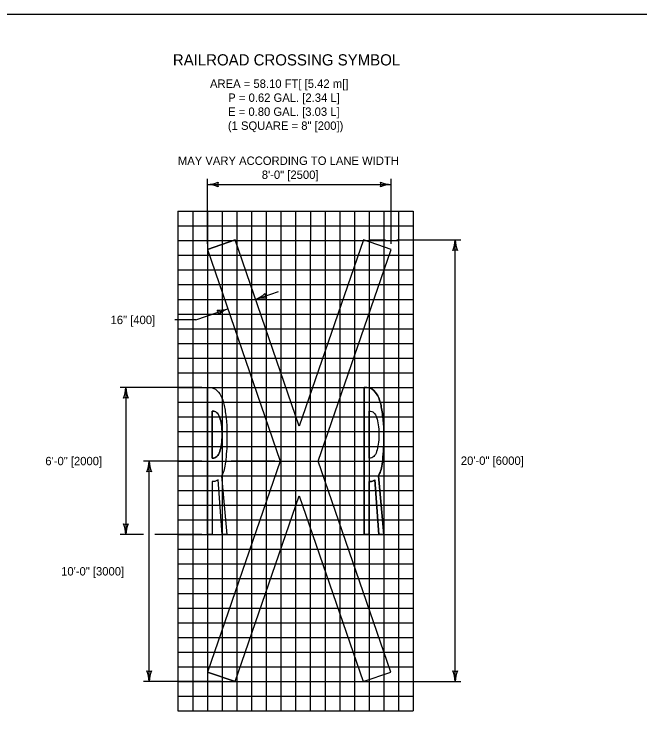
# Model space of a CAD drawing. Extents: x 49948.7 to 50021, y 49977 to 50017.6.
# Drawn here: x 50007.81 to 50012.28, y 49993.97 to 49999 of the extents above; entities that cross this region are included whole.
import ezdxf

# ---------------------------------------------------------------- set-up
doc = ezdxf.new("R2010")
doc.units = 0
for name, color, linetype in [('Level 1', 7, 'Continuous'), ('Level 2', 7, 'Continuous'), ('Level 3', 7, 'Continuous'), ('Level 9', 7, 'Continuous')]:
    doc.layers.add(name, color=color, linetype=linetype)

msp = doc.modelspace()

# ---------------------------------------------------------------- linework, layer by layer
at = {"layer": 'Level 1'}
for p, q in [((50009.1932, 49997.3186), (50009.3909, 49997.3867)), ((50009.3909, 49997.3867), (50009.1932, 49997.3186)), ((50009.8495, 49996.0553), (50009.3909, 49997.3867)), ((50009.8495, 49996.0553), (50009.3909, 49997.3867)), ((50010.3081, 49997.3869), (50009.8495, 49996.0553)), ((50010.3081, 49997.3869), (50009.8495, 49996.0553)), ((50010.5058, 49997.3188), (50010.3081, 49997.3869)), ((50010.5058, 49997.3188), (50010.3081, 49997.3869)), ((50009.1932, 49997.3186), (50009.7138, 49995.8068)), ((50009.1932, 49997.3186), (50009.7138, 49995.8069)), ((50009.1932, 49997.3186), (50009.7138, 49995.8069)), ((50009.9851, 49995.8069), (50010.5058, 49997.3188)), ((50009.9851, 49995.8069), (50010.5058, 49997.3188)), ((50009.1932, 49995.2818), (50009.1932, 49996.3318)), ((50009.1932, 49995.2818), (50009.1932, 49996.3318)), ((50010.3133, 49995.2818), (50010.3133, 49996.3319)), ((50010.3133, 49996.3319), (50010.3133, 49995.2818)), ((50009.2281, 49995.8278), (50009.2281, 49996.1638)), ((50009.2281, 49996.1638), (50009.2281, 49995.8278)), ((50010.3482, 49995.8278), (50010.3482, 49996.1638)), ((50010.3482, 49995.8278), (50010.3482, 49996.1638)), ((50009.7138, 49995.8068), (50009.1949, 49994.2999)), ((50009.7138, 49995.8068), (50009.1949, 49994.2999)), ((50010.504, 49994.2999), (50009.9851, 49995.8068)), ((50010.504, 49994.2999), (50009.9851, 49995.8068)), ((50009.298, 49995.2818), (50009.2692, 49995.673)), ((50009.298, 49995.2818), (50009.2692, 49995.673)), ((50009.2947, 49995.7018), (50009.3329, 49995.2818)), ((50009.2947, 49995.7018), (50009.3329, 49995.2818)), ((50010.4181, 49995.2818), (50010.3893, 49995.673)), ((50010.3893, 49995.673), (50010.4181, 49995.2818)), ((50010.4148, 49995.7018), (50010.453, 49995.2818)), ((50010.453, 49995.2818), (50010.4148, 49995.7018)), ((50009.2281, 49995.6598), (50009.2281, 49995.2818)), ((50009.2281, 49995.6598), (50009.2281, 49995.2818)), ((50010.3482, 49995.6598), (50010.3482, 49995.2818)), ((50010.3482, 49995.2818), (50010.3482, 49995.6598)), ((50009.3926, 49994.2319), (50009.8495, 49995.5584)), ((50009.3926, 49994.2319), (50009.8495, 49995.5584)), ((50009.8495, 49995.5584), (50010.3063, 49994.2319)), ((50009.8495, 49995.5584), (50010.3063, 49994.2319)), ((50009.2281, 49995.2818), (50009.1932, 49995.2818)), ((50009.2281, 49995.2818), (50009.1932, 49995.2818)), ((50009.3329, 49995.2818), (50009.298, 49995.2818)), ((50009.3329, 49995.2818), (50009.298, 49995.2818)), ((50010.3482, 49995.2818), (50010.3133, 49995.2818)), ((50010.3133, 49995.2818), (50010.3482, 49995.2818)), ((50010.453, 49995.2818), (50010.4181, 49995.2818)), ((50010.4181, 49995.2818), (50010.453, 49995.2818)), ((50009.3926, 49994.2319), (50009.1949, 49994.2999)), ((50009.1949, 49994.2999), (50009.3926, 49994.2319)), ((50010.3063, 49994.2319), (50010.504, 49994.2999)), ((50010.3063, 49994.2319), (50010.504, 49994.2999))]:
    msp.add_line(p, q, dxfattribs=at)
msp.add_lwpolyline([(49999.3835, 49998.9992), (50016.7501, 49998.9992), (50016.7501, 49987.7988), (49999.3835, 49987.7988)], close=True, dxfattribs=at)
for points in [[(50009.1932, 49996.3318), (50009.2207, 49996.3343), (50009.2513, 49996.3249), (50009.2939, 49996.2761), (50009.3133, 49996.2081), (50009.3292, 49996.109), (50009.3333, 49996.0383), (50009.3329, 49995.9958)], [(50009.1932, 49996.3318), (50009.2207, 49996.3343), (50009.2513, 49996.3249), (50009.2939, 49996.2761), (50009.3133, 49996.2081), (50009.3292, 49996.109), (50009.3333, 49996.0383), (50009.3329, 49995.9958)], [(50010.3133, 49996.3319), (50010.3407, 49996.3343), (50010.3713, 49996.3249), (50010.414, 49996.2761), (50010.4333, 49996.2081), (50010.4493, 49996.109), (50010.4534, 49996.0383), (50010.453, 49995.9958)], [(50010.453, 49995.9958), (50010.4534, 49996.0383), (50010.4493, 49996.109), (50010.4333, 49996.2081), (50010.414, 49996.2761), (50010.3713, 49996.3249), (50010.3407, 49996.3343), (50010.3133, 49996.3319)], [(50009.2281, 49996.1638), (50009.2422, 49996.1638), (50009.263, 49996.1567), (50009.2834, 49996.1201), (50009.2941, 49996.0668), (50009.2985, 49996.0246), (50009.298, 49995.9958)], [(50009.298, 49995.9958), (50009.2985, 49996.0246), (50009.2941, 49996.0668), (50009.2834, 49996.1201), (50009.263, 49996.1567), (50009.2422, 49996.1638), (50009.2281, 49996.1638)], [(50010.3482, 49996.1638), (50010.3622, 49996.1638), (50010.383, 49996.1567), (50010.4034, 49996.1201), (50010.4142, 49996.0668), (50010.4186, 49996.0246), (50010.4181, 49995.9958)], [(50010.3482, 49996.1638), (50010.3622, 49996.1638), (50010.383, 49996.1567), (50010.4034, 49996.1201), (50010.4142, 49996.0668), (50010.4186, 49996.0246), (50010.4181, 49995.9958)], [(50009.298, 49995.9958), (50009.2985, 49995.9671), (50009.2941, 49995.9248), (50009.2834, 49995.8715), (50009.263, 49995.835), (50009.2422, 49995.8279), (50009.2281, 49995.8278)], [(50009.2281, 49995.8278), (50009.2422, 49995.8279), (50009.263, 49995.835), (50009.2834, 49995.8715), (50009.2941, 49995.9248), (50009.2985, 49995.9671), (50009.298, 49995.9958)], [(50009.3329, 49995.9958), (50009.3335, 49995.9537), (50009.3319, 49995.8976), (50009.3249, 49995.8134), (50009.3176, 49995.7551), (50009.3023, 49995.7145), (50009.2947, 49995.7018), (50009.2947, 49995.7018)], [(50009.3329, 49995.9958), (50009.3335, 49995.9537), (50009.3319, 49995.8976), (50009.3249, 49995.8134), (50009.3176, 49995.7551), (50009.3023, 49995.7145), (50009.2947, 49995.7018), (50009.2947, 49995.7018)], [(50010.4181, 49995.9958), (50010.4186, 49995.9671), (50010.4142, 49995.9248), (50010.4034, 49995.8716), (50010.383, 49995.835), (50010.3622, 49995.8279), (50010.3482, 49995.8278)], [(50010.4181, 49995.9958), (50010.4186, 49995.9671), (50010.4142, 49995.9248), (50010.4034, 49995.8716), (50010.383, 49995.835), (50010.3622, 49995.8279), (50010.3482, 49995.8278)], [(50010.453, 49995.9958), (50010.4536, 49995.9537), (50010.452, 49995.8976), (50010.445, 49995.8134), (50010.4377, 49995.7551), (50010.4224, 49995.7145), (50010.4148, 49995.7018), (50010.4148, 49995.7018)], [(50010.4148, 49995.7018), (50010.4148, 49995.7018), (50010.4224, 49995.7145), (50010.4377, 49995.7551), (50010.445, 49995.8134), (50010.452, 49995.8976), (50010.4536, 49995.9537), (50010.453, 49995.9958)], [(50009.2692, 49995.673), (50009.2692, 49995.673), (50009.2571, 49995.6642), (50009.2436, 49995.6601), (50009.2281, 49995.6598)], [(50009.2692, 49995.673), (50009.2692, 49995.673), (50009.2571, 49995.6642), (50009.2436, 49995.6601), (50009.2281, 49995.6598)], [(50010.3893, 49995.673), (50010.3893, 49995.673), (50010.3772, 49995.6643), (50010.3637, 49995.6601), (50010.3482, 49995.6598)], [(50010.3482, 49995.6598), (50010.3637, 49995.6601), (50010.3772, 49995.6643), (50010.3893, 49995.673), (50010.3893, 49995.673)]]:
    msp.add_open_spline(points, degree=3, dxfattribs=at)
at = {"layer": 'Level 3'}
for p, q in [((50009.1923, 49997.7818), (50010.5058, 49997.7818)), ((50009.1932, 49997.3586), (50009.1932, 49997.8218)), ((50010.5058, 49997.3588), (50010.5058, 49997.8218)), ((50010.3481, 49997.3869), (50010.4658, 49997.3869)), ((50010.5458, 49997.3869), (50011.0027, 49997.3869)), ((50010.9627, 49994.2319), (50010.9627, 49997.3869)), ((50009.5372, 49996.9618), (50009.7012, 49997.0183)), ((50009.1107, 49996.8149), (50009.3395, 49996.8937)), ((50009.1107, 49996.8149), (50008.9607, 49996.8149)), ((50009.1532, 49996.3318), (50008.5712, 49996.3318)), ((50008.6112, 49996.3318), (50008.6112, 49995.2818)), ((50009.1532, 49995.8068), (50008.7378, 49995.8068)), ((50008.7778, 49994.2319), (50008.7778, 49995.8068)), ((50009.6738, 49995.8068), (50009.3637, 49995.8068)), ((50008.7378, 49995.2818), (50008.5712, 49995.2818)), ((50009.1532, 49995.2818), (50008.8178, 49995.2818)), ((50009.2926, 49994.2319), (50008.7378, 49994.2319)), ((50010.4063, 49994.2319), (50011.0026, 49994.2319))]:
    msp.add_line(p, q, dxfattribs=at)
for centre, radius, start, end in [((50009.1817, 49998.0146), 0.233, 272.8273, 292.0772), ((50009.1817, 49998.0145), 0.233, 272.8273, 292.0772), ((50009.1841, 49997.5597), 0.2223, 67.456, 87.6395), ((50009.1841, 49997.5597), 0.2223, 67.456, 87.6395), ((50009.3214, 49997.7818), 0.0548, 162.1388, 197.8612), ((50009.3214, 49997.7818), 0.0548, 162.1388, 197.8612), ((50010.515, 49998.004), 0.2223, 247.456, 267.6395), ((50010.3776, 49997.7818), 0.0548, 342.1388, 17.8612), ((50010.5173, 49997.5491), 0.233, 92.8273, 112.0772), ((50010.7405, 49997.3961), 0.2223, 337.456, 357.6395), ((50011.1954, 49997.3984), 0.233, 182.8273, 202.0772), ((50010.9627, 49997.2587), 0.0548, 72.1388, 107.8612), ((50009.4506, 49997.1781), 0.233, 291.8307, 311.0805), ((50009.6585, 49997.0036), 0.0548, 181.1422, 216.8645), ((50009.6009, 49996.7488), 0.2223, 86.4594, 106.6429), ((50009.2758, 49997.1068), 0.2223, 266.4594, 286.6429), ((50009.2183, 49996.852), 0.0548, 1.1422, 36.8645), ((50009.4262, 49996.6775), 0.233, 111.8307, 131.0805), ((50008.389, 49996.341), 0.2223, 337.456, 357.6395), ((50008.8439, 49996.3433), 0.233, 182.8273, 202.0772), ((50008.6112, 49996.2036), 0.0548, 72.1388, 107.8612), ((50008.5557, 49995.816), 0.2223, 337.456, 357.6395), ((50009.0105, 49995.8183), 0.233, 182.8273, 202.0772), ((50008.7778, 49995.6786), 0.0548, 72.1388, 107.8612), ((50008.6112, 49995.4101), 0.0548, 252.1388, 287.8612), ((50008.3785, 49995.2704), 0.233, 2.8273, 22.0772), ((50008.8333, 49995.2727), 0.2223, 157.456, 177.6395), ((50008.7778, 49994.3601), 0.0548, 252.1388, 287.8612), ((50008.5451, 49994.2204), 0.233, 2.8273, 22.0772), ((50008.9999, 49994.2227), 0.2223, 157.456, 177.6395), ((50010.9627, 49994.3601), 0.0548, 252.1388, 287.8612), ((50010.7299, 49994.2204), 0.233, 2.8273, 22.0772), ((50011.1848, 49994.2227), 0.2223, 157.456, 177.6395)]:
    msp.add_arc(centre, radius, start, end, dxfattribs=at)
at = {"layer": 'Level 9'}
for p, q in [((50008.9832, 49997.5919), (50010.0332, 49997.5919)), ((50008.9832, 49997.5919), (50008.9832, 49997.4869)), ((50009.0882, 49997.5919), (50009.0882, 49997.4869)), ((50009.1932, 49997.5919), (50009.1932, 49997.4869)), ((50009.2982, 49997.5919), (50009.2982, 49997.3818)), ((50009.4032, 49997.5919), (50009.4032, 49997.3818)), ((50009.5082, 49997.5919), (50009.5082, 49997.3818)), ((50009.6132, 49997.5919), (50009.6132, 49997.3818)), ((50009.7182, 49997.5919), (50009.7182, 49997.3818)), ((50009.8227, 49997.5919), (50009.8227, 49994.0218)), ((50009.8232, 49997.5919), (50009.8232, 49997.3818)), ((50009.9282, 49997.5919), (50009.9282, 49997.3818)), ((50010.0332, 49997.5919), (50010.6632, 49997.5919)), ((50010.0332, 49997.5919), (50010.0332, 49997.4868)), ((50010.1382, 49997.5919), (50010.1382, 49997.4868)), ((50010.2432, 49997.5919), (50010.2432, 49997.4868)), ((50010.3482, 49997.5919), (50010.3482, 49997.4868)), ((50010.4532, 49997.5919), (50010.4532, 49997.4868)), ((50010.5582, 49997.5919), (50010.5582, 49997.4868)), ((50010.6632, 49997.5919), (50010.6632, 49994.0218)), ((50008.9832, 49997.4869), (50010.0332, 49997.4869)), ((50008.9832, 49997.4869), (50008.9832, 49994.0218)), ((50009.0882, 49997.4869), (50009.0882, 49994.0218)), ((50009.1932, 49997.4869), (50009.1932, 49994.0218)), ((50010.0332, 49997.4868), (50010.6632, 49997.4868)), ((50010.0332, 49997.4868), (50010.0332, 49996.8568)), ((50010.1382, 49997.4868), (50010.1382, 49994.0218)), ((50010.2432, 49997.4868), (50010.2432, 49994.0218)), ((50010.3482, 49997.4868), (50010.3482, 49994.0218)), ((50010.4532, 49997.4868), (50010.4532, 49994.0218)), ((50010.5582, 49997.4868), (50010.5582, 49994.0218)), ((50008.9832, 49997.3818), (50010.0327, 49997.3818)), ((50009.2982, 49997.3818), (50009.2982, 49994.0218)), ((50009.4032, 49997.3818), (50009.4032, 49994.0218)), ((50009.5077, 49997.3818), (50009.5077, 49995.7704)), ((50009.6127, 49997.3818), (50009.6127, 49995.0718)), ((50009.7177, 49997.3818), (50009.7177, 49995.0718)), ((50009.8227, 49997.3818), (50009.8227, 49995.0718)), ((50009.9277, 49997.3818), (50009.9277, 49995.0718)), ((50010.0327, 49997.3818), (50010.5582, 49997.3818)), ((50008.9827, 49997.2768), (50009.6127, 49997.2768)), ((50008.9832, 49997.2768), (50009.1927, 49997.2768)), ((50009.5758, 49997.2768), (50010.1382, 49997.2768)), ((50010.0755, 49997.2768), (50010.5577, 49997.2768)), ((50010.1377, 49997.2768), (50010.6632, 49997.2768)), ((50008.9827, 49997.1718), (50009.6127, 49997.1718)), ((50008.9832, 49997.1718), (50009.1927, 49997.1718)), ((50009.6127, 49997.1718), (50010.1382, 49997.1718)), ((50010.0335, 49997.1718), (50010.5577, 49997.1718)), ((50010.1377, 49997.1718), (50010.6632, 49997.1718)), ((50008.9832, 49997.0668), (50010.6632, 49997.0668)), ((50008.9832, 49996.9618), (50010.6632, 49996.9618)), ((50008.9832, 49996.8568), (50010.6632, 49996.8568)), ((50010.0332, 49996.8568), (50010.0332, 49994.2318)), ((50008.9832, 49996.7518), (50010.6632, 49996.7518)), ((50008.9832, 49996.6468), (50010.6632, 49996.6468)), ((50008.9832, 49996.5418), (50010.6632, 49996.5418)), ((50008.9832, 49996.4368), (50010.6632, 49996.4368)), ((50008.9832, 49996.3318), (50010.6632, 49996.3318)), ((50008.9832, 49996.2268), (50010.6632, 49996.2268)), ((50008.9832, 49996.1218), (50010.6632, 49996.1218)), ((50008.9832, 49996.0168), (50010.6632, 49996.0168)), ((50008.9832, 49995.9118), (50010.6632, 49995.9118)), ((50008.9832, 49995.8068), (50010.6632, 49995.8068)), ((50009.5077, 49995.7704), (50009.5077, 49994.0218)), ((50008.9832, 49995.7018), (50010.6632, 49995.7018)), ((50008.9832, 49995.5968), (50010.6632, 49995.5968)), ((50008.9832, 49995.4918), (50010.6632, 49995.4918)), ((50008.9832, 49995.3868), (50010.6632, 49995.3868)), ((50008.9832, 49995.2818), (50010.6632, 49995.2818)), ((50008.9827, 49995.1768), (50010.6632, 49995.1768)), ((50008.9827, 49995.1768), (50010.5577, 49995.1768)), ((50008.9827, 49995.0718), (50010.6632, 49995.0718)), ((50009.6127, 49995.0718), (50009.6127, 49994.0218)), ((50009.7177, 49995.0718), (50009.7177, 49994.0218)), ((50009.9277, 49995.0718), (50009.9277, 49994.0218)), ((50008.9832, 49994.9668), (50010.6632, 49994.9668)), ((50010.0327, 49994.9668), (50010.5577, 49994.9668)), ((50008.9832, 49994.8618), (50010.6632, 49994.8618)), ((50010.0332, 49994.8618), (50010.5577, 49994.8618)), ((50008.9832, 49994.7568), (50010.6632, 49994.7568)), ((50010.1377, 49994.7568), (50010.1377, 49994.7568)), ((50008.9832, 49994.6518), (50010.6632, 49994.6518)), ((50008.9832, 49994.5468), (50010.6632, 49994.5468)), ((50008.9832, 49994.4418), (50010.6632, 49994.4418)), ((50008.9832, 49994.3368), (50010.6632, 49994.3368)), ((50008.9832, 49994.2318), (50010.6632, 49994.2318)), ((50010.0332, 49994.2318), (50010.0332, 49994.0218)), ((50008.9832, 49994.1268), (50010.6632, 49994.1268)), ((50008.9832, 49994.0218), (50010.6632, 49994.0218))]:
    msp.add_line(p, q, dxfattribs=at)

# ---------------------------------------------------------------- texts
at = {"layer": 'Level 2'}
for s, height, p in [('RAILROAD CROSSING SYMBOL', 0.08, (50008.9467, 49998.6322)), ('AREA = 58.10 FT[ [5.42 m[]', 0.06, (50009.2119, 49998.4722)), ('P = 0.62 GAL. [2.34 L]', 0.06, (50009.3422, 49998.3722)), ('E = 0.80 GAL. [3.03 L]', 0.06, (50009.3411, 49998.2722)), ('(1 SQUARE = 8" [200])', 0.06, (50009.3394, 49998.1722)), ('MAY VARY ACCORDING TO LANE WIDTH', 0.06, (50008.9825, 49997.9218)), ('8\'-0" [2500]', 0.06, (50009.5816, 49997.8218)), ('16" [400]', 0.06, (50008.5018, 49996.7849)), ('6\'-0" [2000]', 0.06, (50008.0361, 49995.7768)), ('20\'-0" [6000]', 0.06, (50011.0027, 49995.7794)), ('10\'-0" [3000]', 0.06, (50008.1488, 49994.9893))]:
    msp.add_text(s, height=height, dxfattribs=at).set_placement(p)

doc.saveas('drawing.dxf')
